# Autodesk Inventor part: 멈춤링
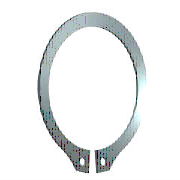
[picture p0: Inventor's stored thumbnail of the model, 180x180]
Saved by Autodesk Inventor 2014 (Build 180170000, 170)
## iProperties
Created: 2009-02
Part Number: 멈춤링
Material: 강, 연강
Description: 리테이닝 링(C형)
Document SubType Name: Modeling
Standard: KS B 1336
Designer: KYOUNG IL JANG
Standards Organization: KS
Language: ko-KR
Size Designation: 22 x 1.2
Categories: <MemberInstance><Categories><Category DisplayName="샤프트 부품" InternalName="7f7aeb1f-a693-4053-b835-cee3144e0d98" Mnemonic="SHFT"><Category DisplayName="써클립" Inter
Density: 7.86 g/cm^3
Appearance: 강철
Mass: 1.8286 g
Surface Area: 5.91219 cm^2
Volume: 0.232646 cm^3
IsCustomPart: 0
Author: KYOUNG IL JANG
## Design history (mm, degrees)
sketch "스케치1"
  geometry: L1 (-6, 0)-(6, 0) reference; L2 (0, 20.189)-(0, -80.536) reference; L3 (-48.09, 0)-(48.09, 0) reference; L4 (-0.5, -21.488)-(-0.5, -25.588); L5 (-0.5, -6.54)-(-0.5, -13.29); L6 (-2.795, 2.7)-(3.672, 2.7); L7 (0.5, -6.54)-(0.5, -13.29); L8 (0.5, -21.488)-(0.5, -25.588); C1 r 1 at (-2, -23.437); C2 r 1 at (2, -23.437); A1 r 10.5 centre (0, -11) between (0.5, -21.488) and (-0.5, -21.488); A2 r 13.025 centre (0, -10.325) between (5.149, -22.289) and (-5.149, -22.289); A3 r 14.597 centre (0, -11) between (-2.318, -25.411) and (-0.5, -25.588); A4 r 2 centre (-2, -23.437) between (-3.97, -23.781) and (-2.318, -25.411); A5 r 2 centre (-5.94, -24.126) between (-3.97, -23.781) and (-5.149, -22.289); A6 r 2 centre (5.94, -24.126) between (5.149, -22.289) and (3.97, -23.781); A7 r 2 centre (2, -23.437) between (2.318, -25.411) and (3.97, -23.781); A8 r 14.597 centre (0, -11) between (0.5, -25.588) and (2.318, -25.411)
  constraints: 16 point on circle, 12 end point, 10 centre point, 9 symmetric about line, 5 point on line, 4 tangent, 3 coincident, 2 horizontal, 1 perpendicular, 1 vertical, 5 other
  dimensions: "d0" = 21 diameter of A1 (= ND); "d1" = 4.1 distance of L4.end L4.start (= SRB2); "d6" = 0.5 distance between parallel lines of L2 L5 (= 0.25 x SD5); "d7" = 2.7 distance between parallel lines of L6 L3 (= SRB1); "d8" = 0.675 distance of A1.centre A2.centre (= 0.25 x SRB1); "d9" = 2 radius of A4 (= SD5); "d10" = 2 radius of A5 (= SD5); "d11" = 1.5 distance from line of L4 A4.centre (= 0.75 x SD5); "d12" = 2 diameter of C1 (= SD5); "d13" = 2 diameter of C2 (= SD5); "d14" = 11 distance from line of A1.centre L1 (= 0.5 x WD)
extrude "본체" new body sketch "스케치1" distance "d2" = 1.2 (= SD); taper "d3" = 0 deg
workaxis "Work Axis1"
workplane "Work Plane1"
body "Solid1"
other parameters: "WD" = 22 (= WDMIN) [user parameter; used in 1 equation term], "SD" = 1.2 [user parameter; used in 1 equation term], "SRB1" = 2.7 [user parameter; used in 2 equation terms], "ND" = 21 [user parameter; used in 1 equation term], "SRB2" = 4.1 [user parameter; used in 1 equation term], "SD5" = 2 [user parameter; used in 6 equation terms], "d15" = 0, "d16" = 0, "d17" = 0, "d41" = 0, "d42" = 0, "WDMIN" = 22 [user parameter; used in 1 equation term], "SD3" = 20.5 [user parameter], "WDMAX" = 24 [user parameter]
